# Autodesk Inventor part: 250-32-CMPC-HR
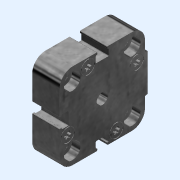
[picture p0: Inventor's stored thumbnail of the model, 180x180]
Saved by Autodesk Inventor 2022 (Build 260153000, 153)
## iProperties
Category: PARTsolutions
Company: METALWORK
Part Number: 250-32-CMPC-HR
Material: Generico
Catalog Web Link: www.cadenas.de
Description: CMPC-HR-
Vendor: METALWORK
Document SubType Name: Modeling
Designer: partserver
Manufacturer: METALWORK
Mass: 26.9446 g
Surface Area: 92.4817 cm^2
Volume: 26.9446 cm^3
Density: 1 g/cm^3
Appearance: Acciaio galvanizzato
PSOL_IDENT_0: {$CADENAS_DATA\23d-libs\metalwork\actuators\comp_cyl_ser_cmpc\parts\cmpc_head_rear.prj},185 {VTYP=3D
PSOL_IDENT_1: },{NB=250-32-CMPC-HR},{LINA=250-32-CMPC-HR},{NN=CMPC-HR},{DATE=18.06.2021 08:06:07},{GEOMDATE=16.03.
PSOL_IDENT_2: 2016 08:37:44},{VERSION=},{LINEID=50},{WBVAR=TYPE,VERSION},{WBNUMERIC=TYPE}  {NB=250-32-CMPC-HR},{LI
PSOL_IDENT_3: NA=250-32-CMPC-HR},{KT=DUMMY},{IDNR=},{DI=32},{TYPE=25},{TX= 23,'Centre distance to UNITOP, male rod'
PSOL_IDENT_4: , 24,'Centre distance to UNITOP, female rod', 25,'Centre distance to ISO, male rod', 26,'Centre dist
PSOL_IDENT_5: ance to ISO, female rod' },{VERSION=0},{VX= '0','Double-acting', '1','Double-acting, through-rod', '
PSOL_IDENT_6: 2','Double-acting, perfored through-rod', '3','Single-acting, retracted rod', '4','Single-acting, ex
PSOL_IDENT_7: tended rod', '5','Single acting, through-rod', '6','Single-acting, perfored through-rod', '7','Doubl
PSOL_IDENT_8: e-acting, non rotating', 'A','Double-acting, through-rod, non rotating'},{A=46.300},{B=32.500},{BB=3
PSOL_IDENT_9: 2.250},{B2=0.000},{C=12.000},{D=47.800},{D1=9.000},{D2=7.600},{D3=7.000},{E=6.000},{H=7.500},{H1=6.9
PSOL_IDENT_10: 50},{H2=5.400},{H3=14.750},{H4=2.800},{L=4.500},{L1=3.700},{L2=1.200},{L3=10.000},{LD=1.700},{O=6.00
PSOL_IDENT_11: 0},{Q=9.728},{R1=7.150},{R2=3.400},{R3=0.300},{R4=0.500},{SW=0.000},{X=18.700},{Y=7.700},{TPL=250}
NB: 250-32-CMPC-HR
NN: CMPC-HR
NBSYN: $TPL.-$DI.-CMPC-HR
LINA: 250-32-CMPC-HR
CATALOG: Metalwork
DI: 32
TYPE: Centre distance to ISO, male rod
VERSION: Double-acting
A: 46.3
B: 32.5
BB: 32.25
B2: 0
C: 12
D: 47.8
D2: 7.6
D3: 7
E: 6
H: 7.5
H1: 6.95
H2: 5.4
H3: 14.75
H4: 2.8
L1: 3.7
L2: 1.2
L3: 10
LD: 1.7
O: 6
Q: 9.728
R1: 7.15
R2: 3.4
R3: 0.3
R4: 0.5
SW: 0
X: 18.7
Y: 7.7
SUPPLIER: METALWORK
ARTICLENO: 250-32-CMPC-HR
BOMINFO: 250-32-CMPC-HR
CREATOR: CADENAS GmbH
Title: 250-32-CMPC-HR
Author: Cadenas PARTsolutions
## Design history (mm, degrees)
sketch "Sketch_1"
  geometry: L1 (-23.15, 16)-(-23.15, 3.1); L2 (-22.75, 2.7)-(-22.15, 2.7); L3 (-21.95, 2.9)-(-21.95, 3.075); L4 (-21.55, 3.475)-(-18.65, 3.475); L5 (-18.25, 3.075)-(-18.25, -3.075); L6 (-18.65, -3.475)-(-21.55, -3.475); L7 (-21.95, -3.075)-(-21.95, -2.9); L8 (-22.15, -2.7)-(-22.75, -2.7); L9 (-23.15, -3.1)-(-23.15, -16); L10 (-16, -23.15)-(-3.1, -23.15); L11 (-2.7, -22.75)-(-2.7, -22.15); L12 (-2.9, -21.95)-(-3.075, -21.95); L13 (-3.475, -21.55)-(-3.475, -18.65); L14 (-3.075, -18.25)-(3.075, -18.25); L15 (3.475, -18.65)-(3.475, -21.55); L16 (3.075, -21.95)-(2.9, -21.95); L17 (2.7, -22.15)-(2.7, -22.75); L18 (3.1, -23.15)-(16, -23.15); L19 (23.15, -16)-(23.15, -10.402); L20 (23.15, -10.402)-(24.65, -10); L21 (24.65, -10)-(24.65, 10); L22 (24.65, 10)-(23.15, 10.402); L23 (23.15, 10.402)-(23.15, 16); L24 (16, 23.15)-(3.1, 23.15); L25 (2.7, 22.75)-(2.7, 22.15); L26 (2.9, 21.95)-(3.075, 21.95); L27 (3.475, 21.55)-(3.475, 18.65); L28 (3.075, 18.25)-(-3.075, 18.25); L29 (-3.475, 18.65)-(-3.475, 21.55); L30 (-3.075, 21.95)-(-2.9, 21.95); L31 (-2.7, 22.15)-(-2.7, 22.75); L32 (-3.1, 23.15)-(-16, 23.15); A1 r 7.15 centre (-16, 16) between (-16, 23.15) and (-23.15, 16); A2 r 0.4 centre (-22.75, 3.1) between (-23.15, 3.1) and (-22.75, 2.7); A3 r 0.2 centre (-22.15, 2.9) between (-22.15, 2.7) and (-21.95, 2.9); A4 r 0.4 centre (-21.55, 3.075) between (-21.55, 3.475) and (-21.95, 3.075); A5 r 0.4 centre (-18.65, 3.075) between (-18.25, 3.075) and (-18.65, 3.475); A6 r 0.4 centre (-18.65, -3.075) between (-18.65, -3.475) and (-18.25, -3.075); A7 r 0.4 centre (-21.55, -3.075) between (-21.95, -3.075) and (-21.55, -3.475); A8 r 0.2 centre (-22.15, -2.9) between (-21.95, -2.9) and (-22.15, -2.7); A9 r 0.4 centre (-22.75, -3.1) between (-22.75, -2.7) and (-23.15, -3.1); A10 r 7.15 centre (-16, -16) between (-23.15, -16) and (-16, -23.15); A11 r 0.4 centre (-3.1, -22.75) between (-3.1, -23.15) and (-2.7, -22.75); A12 r 0.2 centre (-2.9, -22.15) between (-2.7, -22.15) and (-2.9, -21.95); A13 r 0.4 centre (-3.075, -21.55) between (-3.475, -21.55) and (-3.075, -21.95); A14 r 0.4 centre (-3.075, -18.65) between (-3.075, -18.25) and (-3.475, -18.65); A15 r 0.4 centre (3.075, -18.65) between (3.475, -18.65) and (3.075, -18.25); A16 r 0.4 centre (3.075, -21.55) between (3.075, -21.95) and (3.475, -21.55); A17 r 0.2 centre (2.9, -22.15) between (2.9, -21.95) and (2.7, -22.15); A18 r 0.4 centre (3.1, -22.75) between (2.7, -22.75) and (3.1, -23.15); A19 r 7.15 centre (16, -16) between (16, -23.15) and (23.15, -16); A20 r 7.15 centre (16, 16) between (23.15, 16) and (16, 23.15); A21 r 0.4 centre (3.1, 22.75) between (3.1, 23.15) and (2.7, 22.75); A22 r 0.2 centre (2.9, 22.15) between (2.7, 22.15) and (2.9, 21.95); A23 r 0.4 centre (3.075, 21.55) between (3.475, 21.55) and (3.075, 21.95); A24 r 0.4 centre (3.075, 18.65) between (3.075, 18.25) and (3.475, 18.65); A25 r 0.4 centre (-3.075, 18.65) between (-3.475, 18.65) and (-3.075, 18.25); A26 r 0.4 centre (-3.075, 21.55) between (-3.075, 21.95) and (-3.475, 21.55); A27 r 0.2 centre (-2.9, 22.15) between (-2.9, 21.95) and (-2.7, 22.15); A28 r 0.4 centre (-3.1, 22.75) between (-2.7, 22.75) and (-3.1, 23.15)
  constraints: 64 end point, 56 point on circle, 28 centre point
extrude "Extrusion1" join sketch "Sketch_1" distance "d0" = 14.75; taper "d1" = 0 deg
sketch "Sketch2"
  geometry: 1 further point
hole "Hole1" sketch "Sketch2" at (7.5, 10) diameter "d2" = 8.566; stored, may be unused: countersink angle "d6" = 90 deg, drill point angle "d8" = 120 deg; dims "d3" = 9.728, "d4" = 4, "d5" = 2, "d7" = 14.592
sketch "Sketch_7"
  geometry: L1 (14.75, -16.25)-(0, -16.25); L2 (0, -16.25)-(0, -11.75); L3 (0, -11.75)-(4.5, -11.75); L4 (4.5, -11.75)-(4.5, -13.792); L5 (4.5, -13.792)-(14.75, -13.792); L6 (14.75, -13.792)-(14.75, -16.25); L7 (14.75, -16.25)-(0, -16.25)
  constraints: 14 end point
revolve "Revolution1" sketch "Sketch_7" stored, may be unused: angle "d9" = 360 deg
thread "Thread1" dims "d10" = 10.25, "d11" = 0
pattern_linear "Rectangular Pattern1" dims "d14" = 32.5, "d17" = 32.5
sketch "Sketch_13"
  geometry: C1 r 3.8 at (-18.7, 7.7); C2 r 3.5 at (-18.7, 7.7); 2 further points
  constraints: 2 centre point
extrude "Extrusion2" cut sketch "Sketch_13" distance "d18" = 2.8; taper "d19" = 0 deg
pattern_linear "Rectangular Pattern2" dims "d22" = 28.6, "d25" = 28.6
sketch "Sketch_19"
  geometry: L1 (-18.062, 9.384)-(-18.346, 9.1); L2 (-19.054, 9.1)-(-19.338, 9.384); L3 (-19.84, 9.095)-(-19.736, 8.706); L4 (-20.089, 8.094)-(-20.478, 7.99); L5 (-20.478, 7.41)-(-20.089, 7.306); L6 (-19.736, 6.694)-(-19.84, 6.305); L7 (-19.338, 6.016)-(-19.054, 6.3); L8 (-18.346, 6.3)-(-18.062, 6.016); L9 (-17.56, 6.305)-(-17.664, 6.694); L10 (-17.311, 7.306)-(-16.922, 7.41); L11 (-16.922, 7.99)-(-17.311, 8.094); L12 (-17.664, 8.706)-(-17.56, 9.095); A1 r 0.3 centre (-17.85, 9.172) between (-17.56, 9.095) and (-18.062, 9.384); A2 r 0.5 centre (-18.7, 9.454) between (-19.054, 9.1) and (-18.346, 9.1); A3 r 0.3 centre (-19.55, 9.172) between (-19.338, 9.384) and (-19.84, 9.095); A4 r 0.5 centre (-20.219, 8.577) between (-20.089, 8.094) and (-19.736, 8.706); A5 r 0.3 centre (-20.4, 7.7) between (-20.478, 7.99) and (-20.478, 7.41); A6 r 0.5 centre (-20.219, 6.823) between (-19.736, 6.694) and (-20.089, 7.306); A7 r 0.3 centre (-19.55, 6.228) between (-19.84, 6.305) and (-19.338, 6.016); A8 r 0.5 centre (-18.7, 5.946) between (-18.346, 6.3) and (-19.054, 6.3); A9 r 0.3 centre (-17.85, 6.228) between (-18.062, 6.016) and (-17.56, 6.305); A10 r 0.5 centre (-17.181, 6.823) between (-17.311, 7.306) and (-17.664, 6.694); A11 r 0.3 centre (-17, 7.7) between (-16.922, 7.41) and (-16.922, 7.99); A12 r 0.5 centre (-17.181, 8.577) between (-17.664, 8.706) and (-17.311, 8.094)
  constraints: 24 end point, 24 point on circle, 12 centre point
extrude "Extrusion3" cut sketch "Sketch_19" distance "d26" = 1.7; taper "d27" = 0 deg
pattern_linear "Rectangular Pattern3" dims "d30" = 28.6, "d33" = 28.6
sketch "Sketch6"
  geometry: 1 further point
hole "Hole2" sketch "Sketch6" at (0, 0) diameter "d34" = 6; stored, may be unused: countersink angle "d38" = 90 deg, drill point angle "d40" = 0 deg; dims "d35" = 6, "d36" = 4, "d37" = 2, "d39" = 4
node "accessories_XY"
node "accessories_YZ"
node "accessories_ZX"
node "accessories_X"
node "accessories_Y"
node "accessories_Z"
node "accessories_Center"
node "head_r_XY"
node "head_r_YZ"
node "head_r_ZX"
node "head_r_X"
node "head_r_Y"
node "head_r_Z"
node "head_r_Center"
body "Solid1"
other parameters: "d41" = 0, "d42" = 0
